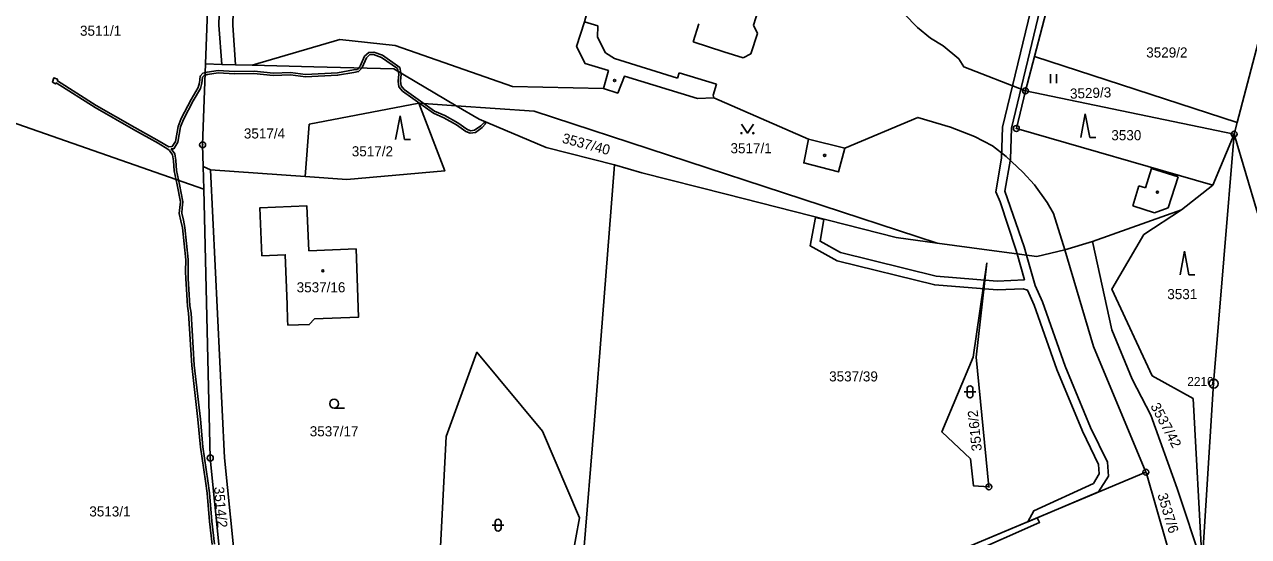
# Model space of a CAD drawing. Extents: x -644096 to -634268, y -1141430 to -1133463.
# Drawn here: x -641396.2 to -641189.8, y -1138337.1 to -1138250.7 of the extents above; entities that cross this region are included whole.
import ezdxf

# ---------------------------------------------------------------- set-up
doc = ezdxf.new("R2010")
doc.units = 0
for name, color, linetype in [('_CIVIL_CONSTRUCTION', 7, 'Continuous'), ('B_Hranice _3D', 7, 'Continuous'), ('M_Svah_Nasyp', 7, 'Continuous'), ('M_Svah_Zarez', 7, 'Continuous'), ('svrsek_osa_sjezdy', 7, 'Continuous'), ('svrsek_osa_VRT', 7, 'Continuous'), ('terminal_VRT', 7, 'Continuous')]:
    doc.layers.add(name, color=color, linetype=linetype)

msp = doc.modelspace()

# ---------------------------------------------------------------- linework, layer by layer
at = {"layer": '_CIVIL_CONSTRUCTION'}
for centre, radius in [((-641227.38, -1138261.88), 0.5), ((-641227.38, -1138261.88), 0.0303), ((-641228.91, -1138268.23), 0.5), ((-641228.91, -1138268.23), 0.0303), ((-641192.16, -1138269.19), 0.5), ((-641366.15, -1138270.99), 0.5), ((-641192.16, -1138269.19), 0.0303), ((-641366.15, -1138270.99), 0.0303), ((-641195.63, -1138311.28), 0.75), ((-641195.63, -1138311.28), 0.03), ((-641364.86, -1138323.83), 0.5), ((-641364.86, -1138323.83), 0.0303), ((-641207.08, -1138326.21), 0.5), ((-641207.08, -1138326.21), 0.0303), ((-641233.54, -1138328.7), 0.5), ((-641233.54, -1138328.7), 0.0303)]:
    msp.add_circle(centre, radius, dxfattribs=at)
at = {"layer": 'B_Hranice _3D'}
for points in [[(-641253.74, -1138205.45), (-641254.22, -1138206.87), (-641222.46, -1138217.42), (-641226.08, -1138246.64), (-641231.24, -1138268.04), (-641231.42, -1138273.25), (-641232.38, -1138278.93), (-641231.65, -1138280.6), (-641229.01, -1138288.64), (-641228.79, -1138289.4), (-641227.17, -1138289.62), (-641227.57, -1138288.18), (-641230.84, -1138278.81), (-641229.92, -1138273.41), (-641229.74, -1138268.2), (-641224.6, -1138246.9), (-641220.76, -1138216.4)], [(-641339.84, -1138258.03), (-641339.32, -1138258.05), (-641339.22, -1138257.93), (-641338.53, -1138256.3), (-641337.95, -1138255.78), (-641337.35, -1138255.74), (-641335.99, -1138256.24), (-641333.26, -1138258.15), (-641333.17, -1138258.61), (-641332.72, -1138258.88), (-641332.9, -1138257.93), (-641335.81, -1138255.88), (-641337.29, -1138255.34), (-641338.11, -1138255.4), (-641338.87, -1138256.06), (-641339.56, -1138257.71)], [(-641340.69, -1138258.37), (-641343.42, -1138258.85), (-641348.79, -1138259.11), (-641351.33, -1138258.77), (-641354.21, -1138258.9), (-641357.47, -1138258.58), (-641360.78, -1138258.64), (-641363.53, -1138258.48), (-641365.41, -1138258.74), (-641365.69, -1138258.82), (-641365.71, -1138259.24), (-641365.33, -1138259.14), (-641363.51, -1138258.88), (-641360.78, -1138259.04), (-641357.49, -1138258.98), (-641354.23, -1138259.3), (-641351.35, -1138259.17), (-641348.81, -1138259.51), (-641343.38, -1138259.25), (-641340.63, -1138258.77), (-641339.84, -1138258.65), (-641339.32, -1138258.05), (-641339.84, -1138258.03), (-641340.04, -1138258.27)], [(-641319.24, -1138267.8), (-641320.29, -1138268.55), (-641320.98, -1138268.62), (-641321.58, -1138268.38), (-641323.09, -1138267.31), (-641325.3, -1138266.06), (-641327.03, -1138265.31), (-641332.15, -1138261.66), (-641332.69, -1138261.04), (-641332.76, -1138260.26), (-641332.68, -1138259.08), (-641332.72, -1138258.88), (-641333.17, -1138258.61), (-641333.08, -1138259.1), (-641333.16, -1138260.26), (-641333.07, -1138261.2), (-641332.43, -1138261.96), (-641327.23, -1138265.65), (-641325.48, -1138266.42), (-641323.31, -1138267.65), (-641321.78, -1138268.74), (-641321.04, -1138269.02), (-641320.15, -1138268.93), (-641318.98, -1138268.1), (-641318.45, -1138267.48), (-641318.42, -1138267.33), (-641318.66, -1138267.21), (-641318.75, -1138267.36)], [(-641261.35, -1138283.6), (-641262.81, -1138283.24), (-641263.66, -1138288.05), (-641259.11, -1138290.57), (-641242.67, -1138294.64), (-641232.16, -1138295.47), (-641227.75, -1138295.28), (-641227.01, -1138295.52), (-641225.9, -1138298.04), (-641222.08, -1138308.89), (-641217.75, -1138319.32), (-641215.04, -1138324.94), (-641214.93, -1138326.5), (-641215.9, -1138328.1), (-641225.97, -1138332.74), (-641226.99, -1138334.6), (-641215.03, -1138329.56), (-641213.39, -1138326.88), (-641213.56, -1138324.54), (-641216.39, -1138318.7), (-641220.68, -1138308.35), (-641224.5, -1138297.48), (-641225.74, -1138294.71), (-641227.17, -1138289.62), (-641228.79, -1138289.4), (-641227.55, -1138293.76), (-641232.14, -1138293.97), (-641242.43, -1138293.16), (-641258.55, -1138289.17), (-641262, -1138287.25)], [(-641225.41, -1138333.93), (-641239.32, -1138339.79), (-641238.67, -1138343.28), (-641236.71, -1138353.82), (-641235.85, -1138353.67), (-641237.92, -1138340.99), (-641237.43, -1138340.2), (-641224.98, -1138334.7)]]:
    msp.add_lwpolyline(points, close=True, dxfattribs=at)
for points in [[(-641362.9, -1138234.32), (-641363.43, -1138250.79), (-641362.92, -1138257.43), (-641360.59, -1138257.49), (-641361.03, -1138250.84), (-641360.65, -1138234.33)], [(-641364.13, -1138338.37), (-641364.57, -1138334.47), (-641365, -1138329.7), (-641365.28, -1138327.68), (-641366.13, -1138321.96), (-641366.53, -1138317.27), (-641367.58, -1138308.16), (-641368.11, -1138299.37), (-641368.29, -1138298.15), (-641368.46, -1138295.32), (-641368.6, -1138293.61), (-641368.61, -1138292.37), (-641368.6, -1138290.37), (-641369.14, -1138284.92), (-641369.4, -1138283.72), (-641369.68, -1138282.54), (-641369.58, -1138281.62), (-641369.46, -1138280.62), (-641370.06, -1138277.67), (-641370.55, -1138275.31), (-641370.68, -1138273.65), (-641370.86, -1138272.5), (-641371.45, -1138271.69), (-641371.02, -1138271.65), (-641370.32, -1138270.55), (-641369.88, -1138267.98), (-641369.39, -1138266.72), (-641367.72, -1138263.56), (-641366.52, -1138261.48), (-641366.3, -1138260.6), (-641366.19, -1138259.58), (-641365.91, -1138259.29), (-641365.71, -1138259.24), (-641365.69, -1138258.82), (-641366.13, -1138258.93), (-641366.57, -1138259.4), (-641366.7, -1138260.52), (-641366.9, -1138261.32), (-641368.08, -1138263.36), (-641369.75, -1138266.56), (-641370.26, -1138267.88), (-641370.7, -1138270.41), (-641371.26, -1138271.27), (-641371.85, -1138271.34), (-641373.47, -1138270.36), (-641377.6, -1138268.06), (-641384.09, -1138264.36), (-641390.64, -1138260.21), (-641390.65, -1138259.91), (-641391.27, -1138259.72), (-641391.47, -1138260.45), (-641390.94, -1138260.71), (-641390.84, -1138260.55), (-641384.29, -1138264.7), (-641377.8, -1138268.4), (-641373.67, -1138270.7), (-641372.01, -1138271.71), (-641371.75, -1138271.95), (-641371.24, -1138272.66), (-641371.08, -1138273.69), (-641370.95, -1138275.37), (-641370.46, -1138277.75), (-641369.86, -1138280.64), (-641369.98, -1138281.58), (-641370.08, -1138282.56), (-641369.8, -1138283.8), (-641369.54, -1138284.98), (-641369, -1138290.39), (-641369.01, -1138292.37), (-641369, -1138293.63), (-641368.86, -1138295.34)], [(-641368.86, -1138295.34), (-641368.69, -1138298.19), (-641368.51, -1138299.41), (-641367.98, -1138308.2), (-641366.93, -1138317.31), (-641366.53, -1138322), (-641365.68, -1138327.74), (-641365.4, -1138329.74), (-641364.97, -1138334.51), (-641364.53, -1138338.41)]]:
    msp.add_lwpolyline(points, dxfattribs=at)
at = {"layer": 'M_Svah_Nasyp'}
for p, q in [((-641273.24, -1138250.84), (-641272.43, -1138248.33)), ((-641301.77, -1138250.26), (-641299.5, -1138250.93)), ((-641299.5, -1138250.93), (-641299.56, -1138252.85)), ((-641283.44, -1138253.65), (-641282.46, -1138250.58)), ((-641272.56, -1138252.21), (-641273.69, -1138255.63)), ((-641272.56, -1138252.21), (-641273.24, -1138250.84)), ((-641299.56, -1138252.85), (-641298.22, -1138255.5)), ((-641278.27, -1138255.33), (-641283.44, -1138253.65)), ((-641298.22, -1138255.5), (-641296.71, -1138256.42)), ((-641275.01, -1138256.31), (-641278.27, -1138255.33)), ((-641273.69, -1138255.63), (-641275.01, -1138256.31)), ((-641296.71, -1138256.42), (-641286.03, -1138259.77)), ((-641286.03, -1138259.77), (-641285.75, -1138258.84)), ((-641285.75, -1138258.84), (-641279.47, -1138260.75)), ((-641279.47, -1138260.75), (-641280.06, -1138262.6)), ((-641280.06, -1138262.6), (-641279.95, -1138263.05)), ((-641263.94, -1138270.07), (-641257.83, -1138271.59)), ((-641207.11, -1138278.23), (-641206.14, -1138274.99)), ((-641206.14, -1138274.99), (-641201.63, -1138276.41)), ((-641201.63, -1138276.41), (-641203.3, -1138281.6)), ((-641209.27, -1138281.29), (-641208.24, -1138277.9)), ((-641208.24, -1138277.9), (-641207.11, -1138278.23)), ((-641205.6, -1138282.47), (-641209.27, -1138281.29)), ((-641203.3, -1138281.6), (-641205.6, -1138282.47))]:
    msp.add_line(p, q, dxfattribs=at)
at = {"layer": 'M_Svah_Zarez'}
for centre in [(-641296.66, -1138260.15), (-641261.24, -1138272.78), (-641205.12, -1138278.99), (-641345.88, -1138292.25)]:
    msp.add_circle(centre, 0.175, dxfattribs=at)
at = {"layer": 'svrsek_osa_sjezdy'}
for p, q in [((-641223.14, -1138260.58), (-641223.14, -1138259.08)), ((-641222.14, -1138260.58), (-641222.14, -1138259.08)), ((-641332.85, -1138266.09), (-641333.6, -1138270.09)), ((-641332.1, -1138270.09), (-641332.85, -1138266.09)), ((-641217.28, -1138265.79), (-641218.03, -1138269.79)), ((-641216.53, -1138269.79), (-641217.28, -1138265.79)), ((-641332.1, -1138270.09), (-641331.1, -1138270.09)), ((-641216.53, -1138269.79), (-641215.53, -1138269.79)), ((-641200.55, -1138288.95), (-641201.3, -1138292.95)), ((-641199.8, -1138292.95), (-641200.55, -1138288.95)), ((-641199.8, -1138292.95), (-641198.8, -1138292.95)), ((-641237.72, -1138312.68), (-641235.72, -1138312.68)), ((-641237.22, -1138312.18), (-641237.22, -1138313.18)), ((-641236.22, -1138313.18), (-641236.22, -1138312.18)), ((-641343.97, -1138315.42), (-641342.22, -1138315.42)), ((-641316.82, -1138334.65), (-641316.82, -1138335.65)), ((-641315.82, -1138335.65), (-641315.82, -1138334.65)), ((-641317.32, -1138335.15), (-641315.32, -1138335.15))]:
    msp.add_line(p, q, dxfattribs=at)
msp.add_lwpolyline([(-641275.26, -1138267.53), (-641274.26, -1138269.03), (-641273.26, -1138267.53)], dxfattribs=at)
for centre, radius in [((-641275.26, -1138269.03), 0.1), ((-641273.26, -1138269.03), 0.1), ((-641343.97, -1138314.67), 0.75)]:
    msp.add_circle(centre, radius, dxfattribs=at)
for centre, start, end in [((-641236.72, -1138312.18), 0, 180), ((-641236.72, -1138313.18), 180, 359.9879), ((-641316.32, -1138334.65), 0, 180), ((-641316.32, -1138335.65), 180, 359.9879)]:
    msp.add_arc(centre, 0.5, start, end, dxfattribs=at)
at = {"layer": 'terminal_VRT'}
for p, q in [((-641191.65, -1138267.26), (-641185.53, -1138243.91)), ((-641225.85, -1138256.09), (-641223.24, -1138246.16)), ((-641227.38, -1138261.88), (-641225.85, -1138256.09)), ((-641225.85, -1138256.09), (-641191.65, -1138267.26)), ((-641227.38, -1138261.88), (-641192.16, -1138269.19)), ((-641329.71, -1138263.96), (-641348.18, -1138267.52)), ((-641329.71, -1138263.96), (-641323.36, -1138264.41)), ((-641404.73, -1138264.91), (-641365.97, -1138278.49)), ((-641348.18, -1138267.52), (-641348.83, -1138276.35)), ((-641192.16, -1138269.19), (-641191.65, -1138267.26)), ((-641195.76, -1138277.82), (-641192.16, -1138269.19)), ((-641365.97, -1138278.49), (-641366.06, -1138274.64)), ((-641364.8, -1138275.19), (-641366.06, -1138274.64)), ((-641364.8, -1138275.19), (-641348.83, -1138276.35)), ((-641201.04, -1138281.97), (-641195.76, -1138277.82)), ((-641220.75, -1138288.72), (-641216.06, -1138287.31)), ((-641207.08, -1138326.21), (-641239.32, -1138339.79))]:
    msp.add_line(p, q, dxfattribs=at)
for points in [[(-641364.46, -1138225.53), (-641364.47, -1138226), (-641365.64, -1138257.36)], [(-641227.38, -1138261.88), (-641237.78, -1138257.82), (-641238.63, -1138256.49), (-641241.24, -1138254.32), (-641243.39, -1138253.03), (-641245.6, -1138251.19), (-641250.03, -1138246.68), (-641251.21, -1138245.15), (-641252.46, -1138243), (-641252.87, -1138241.63), (-641252.58, -1138239.21), (-641252.13, -1138237.25), (-641259.54, -1138231.46), (-641262.19, -1138239.58), (-641267.72, -1138237.85), (-641268.59, -1138238.29)], [(-641298.53, -1138261.51), (-641297.72, -1138258.48), (-641301.63, -1138257.28), (-641303.08, -1138254.39), (-641301.77, -1138250.26), (-641299.16, -1138240.75), (-641298.26, -1138237.9), (-641291.98, -1138234.65), (-641288.18, -1138235.93), (-641287.81, -1138234.69), (-641286.25, -1138233.89)], [(-641298.53, -1138261.51), (-641313.91, -1138261.15), (-641333.66, -1138254.27), (-641343.02, -1138253.24), (-641357.79, -1138257.56)], [(-641366.06, -1138274.64), (-641366.15, -1138270.99), (-641365.64, -1138257.36)], [(-641365.64, -1138257.36), (-641362.92, -1138257.43), (-641360.59, -1138257.49), (-641357.79, -1138257.56)], [(-641357.79, -1138257.56), (-641347.38, -1138257.83), (-641333.89, -1138258.19), (-641323.36, -1138264.41)], [(-641220.75, -1138288.72), (-641222.63, -1138282.6), (-641223.71, -1138280.72), (-641225.85, -1138277.77), (-641227.8, -1138275.6), (-641230.62, -1138272.94), (-641232.93, -1138271.16), (-641235.94, -1138269.58), (-641240.04, -1138268.03), (-641245.54, -1138266.37), (-641257.83, -1138271.59), (-641258.91, -1138275.56), (-641264.77, -1138274.06), (-641263.94, -1138270.07), (-641279.95, -1138263.05), (-641282.66, -1138263.21), (-641295.02, -1138259.43), (-641296.13, -1138262.26), (-641298.53, -1138261.51)], [(-641195.76, -1138277.82), (-641228.91, -1138268.23), (-641227.38, -1138261.88)], [(-641348.83, -1138276.35), (-641341.85, -1138276.84), (-641325.3, -1138275.41), (-641329.71, -1138263.96)], [(-641323.36, -1138264.41), (-641310.26, -1138265.33), (-641242.29, -1138287.58)], [(-641323.36, -1138264.41), (-641319.51, -1138266.68), (-641308.22, -1138271.44), (-641296.67, -1138274.39)], [(-641197.59, -1138341.7), (-641195.63, -1138311.28), (-641192.16, -1138269.19)], [(-641196.58, -1138347.41), (-641191.59, -1138341.56), (-641173.99, -1138341.13), (-641177.7, -1138295.65), (-641188.26, -1138282.45), (-641192.16, -1138269.19)], [(-641296.67, -1138274.39), (-641298.68, -1138300.29), (-641300.1, -1138318.17), (-641301.88, -1138339.41)], [(-641242.29, -1138287.58), (-641249.16, -1138286.65), (-641277.85, -1138279.32), (-641292.08, -1138275.72), (-641296.67, -1138274.39)], [(-641359.45, -1138353.85), (-641362.46, -1138323.77), (-641364.8, -1138275.19)], [(-641365.97, -1138278.49), (-641364.86, -1138323.83), (-641361.82, -1138354.02)], [(-641356.16, -1138289.7), (-641356.48, -1138281.6), (-641348.55, -1138281.29), (-641348.22, -1138288.87), (-641340.27, -1138288.55), (-641339.85, -1138300.06), (-641347.28, -1138300.36), (-641348.18, -1138301.32), (-641351.77, -1138301.4), (-641351.84, -1138300.53), (-641351.89, -1138297.95), (-641352.2, -1138289.54), (-641356.16, -1138289.7)], [(-641216.06, -1138287.31), (-641212.73, -1138286.1), (-641201.04, -1138281.97)], [(-641201.04, -1138281.97), (-641207.4, -1138286.15), (-641212.8, -1138295.35), (-641206, -1138309.94), (-641199.11, -1138313.8), (-641197.59, -1138341.7)], [(-641197.59, -1138341.7), (-641201.77, -1138328.98), (-641206.23, -1138316.59), (-641209.4, -1138310.55), (-641212.78, -1138302.2), (-641216.06, -1138287.31)], [(-641242.29, -1138287.58), (-641233.47, -1138288.77), (-641225.48, -1138289.85), (-641220.75, -1138288.72)], [(-641220.75, -1138288.72), (-641215.88, -1138305.03), (-641207.08, -1138326.21)], [(-641233.88, -1138290.92), (-641236.21, -1138306.84), (-641241.5, -1138319.43), (-641236.62, -1138323.98), (-641236.14, -1138328.52), (-641233.54, -1138328.7), (-641235.71, -1138306.79), (-641233.88, -1138290.92)], [(-641309.21, -1138348.15), (-641308.19, -1138343.85), (-641304.46, -1138344.04), (-641302.57, -1138333.94), (-641308.83, -1138319.3), (-641319.9, -1138306), (-641325.1, -1138320.22), (-641326.21, -1138342.07), (-641324.33, -1138349.9)], [(-641207.08, -1138326.21), (-641206.98, -1138326.43), (-641200.22, -1138349.93), (-641199.11, -1138357.49), (-641200.01, -1138363.84), (-641198.13, -1138374.51)]]:
    msp.add_lwpolyline(points, dxfattribs=at)

# ---------------------------------------------------------------- texts
at = {"layer": '_CIVIL_CONSTRUCTION'}
msp.add_text('2210', height=1.5, dxfattribs=at).set_placement((-641200.08, -1138311.66))
at = {"layer": 'svrsek_osa_VRT'}
for s, p in [('3511/1', (-641386.83, -1138252.6)), ('3529/2', (-641207, -1138256.27)), ('3517/4', (-641359.19, -1138269.93)), ('3530', (-641212.89, -1138270.22)), ('3517/1', (-641277.12, -1138272.42)), ('3517/2', (-641340.99, -1138272.94)), ('3537/16', (-641350.29, -1138295.88)), ('3531', (-641203.45, -1138297.03)), ('3537/39', (-641260.48, -1138310.91)), ('3537/17', (-641348.08, -1138320.17)), ('3513/1', (-641385.26, -1138333.69))]:
    msp.add_text(s, height=1.7, dxfattribs=at).set_placement(p)
for s, rotation, p in [('3529/3', 2, (-641219.83, -1138263.22)), ('3537/40', 345, (-641305.64, -1138270.62)), ('3516/2', 96, (-641234.72, -1138322.58)), ('3537/42', 298, (-641206.34, -1138315.07)), ('3514/2', 275, (-641364.24, -1138328.74)), ('3537/6', 287, (-641205.14, -1138330.03))]:
    msp.add_text(s, height=1.7, rotation=rotation, dxfattribs=at).set_placement(p)

doc.saveas('drawing.dxf')
